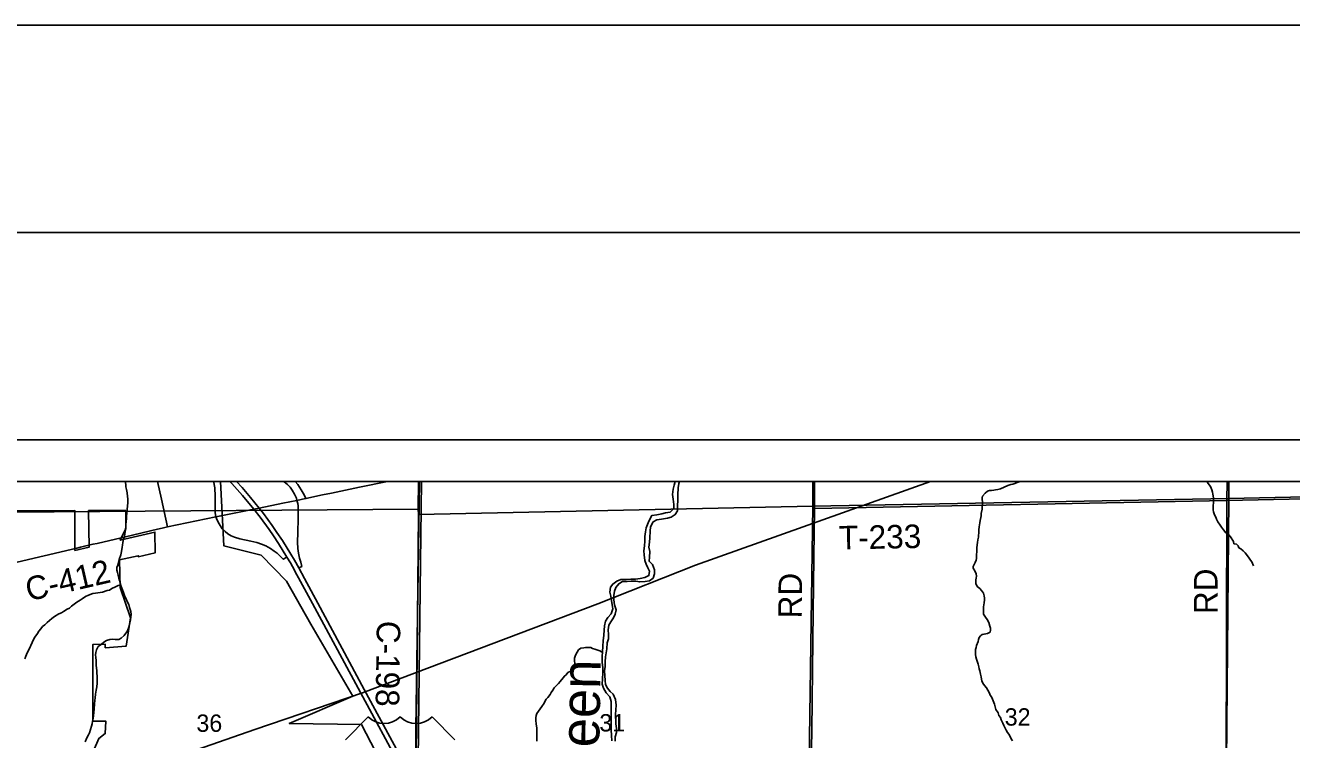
# Model space of a CAD drawing. Extents: x 36.7 to 70.7, y 0 to 22.
# Drawn here: x 40.424 to 43.478, y 20.274 to 21.997 of the extents above; entities that cross this region are included whole.
import ezdxf

# ---------------------------------------------------------------- set-up
doc = ezdxf.new("R2010")
doc.units = 0
for name, color, linetype in [('Default', 7, 'Continuous'), ('GM_X_City_Street', 7, 'Continuous'), ('GM_X_County_Road', 7, 'Continuous'), ('GM_X_County_Road_Text', 7, 'Continuous'), ('GM_X_Interchange_Ramps', 7, 'Continuous'), ('GM_X_Minor_River', 7, 'Continuous'), ('GM_X_Minor_River_Text', 7, 'Continuous'), ('GM_X_Rail_Line', 7, 'Continuous'), ('GM_X_Section', 7, 'Continuous'), ('GM_X_Section_Text', 7, 'Continuous'), ('GM_X_State_Route', 7, 'Continuous'), ('GM_X_Township_Road', 7, 'Continuous'), ('GM_X_Township_Road_Text', 7, 'Continuous'), ('GM_X_US_Route', 7, 'Continuous'), ('GM_X_US_Shield', 7, 'Continuous'), ('SH_Border', 7, 'Continuous'), ('SH_Cut_Line', 7, 'Continuous'), ('SH_Data', 7, 'Continuous')]:
    doc.layers.add(name, color=color, linetype=linetype)

msp = doc.modelspace()

# ---------------------------------------------------------------- linework, layer by layer
at = {"layer": 'Default'}
for points in [[(41.36, 20.0684), (41.2347, 20.3107), (41.0604, 20.3126), (41.214, 20.3785), (41.1126, 20.5525), (41.0537, 20.6559), (40.9928, 20.719), (40.9027, 20.7415), (40.895, 20.8969), (40.3795, 20.8969)], [(40.3778, 20.8261), (40.5438, 20.8262), (40.5437, 20.7305), (40.5783, 20.7382), (40.5767, 20.8262), (40.6662, 20.8262), (40.6662, 20.783), (40.6532, 20.755), (40.7365, 20.7744), (40.7376, 20.7245), (40.6963, 20.7149), (40.6963, 20.7176), (40.6514, 20.7072), (40.6526, 20.6409), (40.6779, 20.5674), (40.6671, 20.4991), (40.617, 20.4956), (40.617, 20.5041), (40.5872, 20.5036), (40.5873, 20.3184), (40.6185, 20.3181), (40.6169, 20.2884), (40.6016, 20.2769), (40.5883, 20.2469)]]:
    msp.add_lwpolyline(points, dxfattribs=at)
for points in [[(41.3719, 20.8969), (40.3859, 20.8969), (40.3846, 20.8226), (41.3712, 20.8297)], [(42.3233, 20.8969), (41.3719, 20.8969), (41.3712, 20.8297), (41.3719, 20.8169), (42.3229, 20.8368)], [(43.3265, 20.8969), (42.3233, 20.8969), (42.3229, 20.8368), (43.3259, 20.8559)], [(44.3297, 20.8969), (43.3265, 20.8969), (43.3259, 20.8559), (44.3293, 20.877)]]:
    msp.add_lwpolyline(points, close=True, dxfattribs=at)
at = {"layer": 'GM_X_City_Street'}
msp.add_lwpolyline([(40.7671, 20.787), (40.7529, 20.8536), (40.7428, 20.8969)], dxfattribs=at)
at = {"layer": 'GM_X_County_Road'}
for points in [[(41.3724, 20.2907), (41.3724, 20.2976), (41.3772, 20.7013), (41.3795, 20.8969)], [(40.7545, 20.7841), (40.7671, 20.787), (40.8833, 20.811)], [(40.6661, 20.7634), (40.7428, 20.7814), (40.7545, 20.7841)], [(40.2321, 20.662), (40.5482, 20.7359), (40.5572, 20.738)], [(40.5572, 20.738), (40.5872, 20.745), (40.597, 20.7473)], [(40.597, 20.7473), (40.6553, 20.7609), (40.6661, 20.7634)], [(41.5658, 19.8236), (41.565, 19.832), (41.5635, 19.8393), (41.5617, 19.8452), (41.5575, 19.8561), (41.5522, 19.8667), (41.5429, 19.8845), (41.5299, 19.909), (41.5148, 19.9368), (41.4954, 19.9722), (41.4697, 20.0201), (41.4396, 20.0758), (41.4107, 20.1293), (41.3858, 20.1754), (41.3766, 20.1942), (41.3724, 20.2103), (41.3715, 20.2274), (41.3724, 20.2907)]]:
    msp.add_lwpolyline(points, dxfattribs=at)
at = {"layer": 'GM_X_Interchange_Ramps'}
for points in [[(41.0791, 20.851), (41.078, 20.8566), (41.0735, 20.8663), (41.0677, 20.8757), (41.0626, 20.8829), (41.0566, 20.8894), (41.0483, 20.8961), (41.0469, 20.8969)], [(41.0838, 20.6879), (41.0912, 20.6918), (41.0883, 20.7017), (41.0855, 20.7119), (41.0829, 20.7236), (41.0816, 20.7346), (41.0808, 20.7502), (41.0813, 20.7738), (41.082, 20.8072), (41.0823, 20.8252), (41.0823, 20.8375), (41.0815, 20.8433), (41.0791, 20.851)], [(40.8833, 20.811), (40.8851, 20.8071), (40.889, 20.7988), (40.8936, 20.7904), (40.8992, 20.7826), (40.9007, 20.7812)], [(40.9007, 20.7812), (40.9057, 20.776), (40.9128, 20.7702), (40.9205, 20.7657), (40.9289, 20.7619), (40.9417, 20.7584), (40.968, 20.7526), (40.9826, 20.7492), (40.9937, 20.7455), (41.0039, 20.741), (41.0151, 20.735), (41.0242, 20.7289), (41.0315, 20.7234), (41.039, 20.7165), (41.0462, 20.7089), (41.0547, 20.7144)]]:
    msp.add_lwpolyline(points, dxfattribs=at)
at = {"layer": 'GM_X_Minor_River'}
for points in [[(40.6653, 20.8969), (40.6662, 20.8894), (40.6669, 20.8837), (40.6683, 20.8769), (40.6694, 20.8693), (40.6704, 20.8601), (40.6711, 20.8544), (40.671, 20.8465), (40.6705, 20.8366), (40.6701, 20.8309), (40.6688, 20.8207), (40.668, 20.8123), (40.6679, 20.807), (40.6671, 20.7991), (40.6666, 20.7937), (40.6662, 20.7877), (40.6657, 20.7805), (40.6641, 20.7702), (40.6629, 20.7642), (40.6605, 20.7581), (40.6593, 20.7498), (40.6585, 20.7433), (40.6577, 20.738)], [(41.8964, 20.6562), (41.9058, 20.6544), (41.9191, 20.6556), (41.9294, 20.6572), (41.9379, 20.6634), (41.9412, 20.674), (41.9415, 20.6834), (41.9365, 20.6965), (41.9284, 20.7043), (41.929, 20.7142), (41.9298, 20.7278), (41.9278, 20.7381), (41.9293, 20.7506), (41.9299, 20.7608), (41.9307, 20.7764), (41.9318, 20.7874), (41.9378, 20.799), (41.947, 20.8044), (41.958, 20.8053), (41.9725, 20.8079), (41.9817, 20.8107), (41.9914, 20.8169), (41.9969, 20.8254), (41.9968, 20.8368), (41.9976, 20.8524), (41.9976, 20.8642), (41.998, 20.8809), (42.0002, 20.8918), (42.0016, 20.8969)], [(41.9915, 20.8969), (41.9887, 20.8879), (41.9862, 20.8778), (41.9847, 20.8649), (41.9867, 20.8542), (41.9878, 20.8413), (41.988, 20.8314), (41.979, 20.8225), (41.968, 20.8213), (41.9588, 20.8185), (41.9473, 20.8162), (41.9352, 20.8146), (41.93, 20.806), (41.9263, 20.797), (41.9215, 20.785), (41.9193, 20.7748), (41.9179, 20.7642), (41.9183, 20.7528), (41.9169, 20.7411), (41.9158, 20.729), (41.9163, 20.7194), (41.9178, 20.7061), (41.9214, 20.6973)], [(42.8251, 20.8969), (42.8232, 20.8962), (42.8156, 20.894), (42.8103, 20.8918), (42.8057, 20.8903), (42.8008, 20.8893), (42.7932, 20.8867), (42.7848, 20.883), (42.7756, 20.8789), (42.7695, 20.8774), (42.7638, 20.8767), (42.7597, 20.8757), (42.754, 20.875), (42.749, 20.8746), (42.7441, 20.8732), (42.7383, 20.8683), (42.7326, 20.8615)], [(43.2724, 20.8969), (43.2746, 20.894), (43.2787, 20.8883), (43.2817, 20.8841), (43.2851, 20.8761), (43.2865, 20.8708), (43.2876, 20.8662), (43.2883, 20.862), (43.289, 20.8567), (43.2889, 20.8457), (43.2884, 20.8381), (43.2887, 20.8332), (43.2887, 20.8278), (43.289, 20.8233), (43.292, 20.8164), (43.2946, 20.8107), (43.2968, 20.8057), (43.2994, 20.7996), (43.3053, 20.7916), (43.3083, 20.7863), (43.3132, 20.7797), (43.3192, 20.7729), (43.3252, 20.769), (43.33, 20.7629), (43.3371, 20.7518), (43.3386, 20.7464), (43.3446, 20.7452), (43.3484, 20.741), (43.3506, 20.7368), (43.3551, 20.7345), (43.3608, 20.7291), (43.3653, 20.7241), (43.3712, 20.7169), (43.3754, 20.7115), (43.3787, 20.7069), (43.3817, 20.7027), (43.3861, 20.6928)], [(42.7326, 20.8615), (42.7314, 20.857), (42.7317, 20.8524), (42.7324, 20.8479), (42.7319, 20.8403), (42.7315, 20.8346), (42.7311, 20.83), (42.7294, 20.8194), (42.729, 20.8137), (42.7282, 20.8096), (42.7266, 20.8024), (42.7258, 20.7967), (42.7245, 20.7868), (42.7233, 20.78), (42.7236, 20.7716), (42.7228, 20.7667), (42.7223, 20.7625), (42.7211, 20.7557), (42.7199, 20.7497), (42.7191, 20.744), (42.7186, 20.7368), (42.7185, 20.7284), (42.718, 20.7189), (42.7176, 20.7106), (42.7168, 20.7064), (42.7148, 20.7011), (42.7125, 20.6962), (42.7098, 20.6913), (42.7097, 20.6871), (42.7134, 20.6807), (42.7168, 20.6742), (42.7178, 20.6685), (42.7167, 20.6635), (42.7162, 20.6594), (42.7158, 20.6544), (42.7165, 20.6502), (42.7195, 20.6434), (42.7255, 20.6384), (42.73, 20.6334), (42.7348, 20.6273), (42.7363, 20.6208), (42.737, 20.6151), (42.7373, 20.6109), (42.7365, 20.6037), (42.7356, 20.5992), (42.7348, 20.5939), (42.7344, 20.5874), (42.7347, 20.5813), (42.735, 20.5764), (42.7395, 20.5691), (42.7432, 20.5638), (42.7473, 20.5565), (42.7502, 20.5478), (42.7513, 20.5424), (42.7513, 20.5383), (42.7508, 20.5333), (42.7443, 20.5296), (42.7402, 20.5289), (42.736, 20.5286), (42.7314, 20.5275), (42.7272, 20.5241), (42.7245, 20.52), (42.7226, 20.5158), (42.7214, 20.5109), (42.7178, 20.501), (42.717, 20.4965), (42.7151, 20.4912), (42.7153, 20.4794), (42.7164, 20.4737), (42.7178, 20.4676), (42.72, 20.4608), (42.7215, 20.4558), (42.7233, 20.4494), (42.7244, 20.4448), (42.7259, 20.4398), (42.7273, 20.4322), (42.7287, 20.4254), (42.7298, 20.4201), (42.7309, 20.4155), (42.7331, 20.4098), (42.7372, 20.4044), (42.7417, 20.3991), (42.7451, 20.3933), (42.7488, 20.3857), (42.751, 20.3811), (42.7536, 20.3769), (42.7562, 20.3712), (42.7595, 20.3636), (42.761, 20.3594), (42.7628, 20.3533), (42.7646, 20.3468), (42.7702, 20.3388), (42.7713, 20.3323), (42.7758, 20.3269), (42.7776, 20.322), (42.7809, 20.3136), (42.7835, 20.3079), (42.7895, 20.2964), (42.7925, 20.2915), (42.7958, 20.2869), (42.7999, 20.28)], [(40.6577, 20.738), (40.6564, 20.7274), (40.6544, 20.7195), (40.6505, 20.7085), (40.6473, 20.6949), (40.645, 20.6888), (40.6449, 20.6824), (40.6463, 20.6767), (40.6478, 20.671), (40.6496, 20.6637), (40.6514, 20.6576), (40.6529, 20.6515), (40.6551, 20.6435), (40.6584, 20.6355), (40.6617, 20.6264), (40.6643, 20.6195), (40.6672, 20.6134), (40.6694, 20.6069), (40.6739, 20.5997), (40.6757, 20.5928), (40.6783, 20.5833), (40.679, 20.5761), (40.6781, 20.5632), (40.6765, 20.556), (40.6737, 20.5454), (40.6713, 20.539), (40.6686, 20.5337), (40.6621, 20.5254), (40.6556, 20.519), (40.6494, 20.5157), (40.6411, 20.5154), (40.6354, 20.5162), (40.6282, 20.5155), (40.6202, 20.5129), (40.6133, 20.5088), (40.6072, 20.5036), (40.5999, 20.4984), (40.5961, 20.4908), (40.5945, 20.4844), (40.5933, 20.4787), (40.5939, 20.4722), (40.595, 20.465), (40.5953, 20.4582), (40.5952, 20.4529), (40.5962, 20.4403), (40.5965, 20.4331), (40.5972, 20.4274), (40.5975, 20.4202), (40.5974, 20.4103), (40.5966, 20.4012), (40.5953, 20.3929), (40.5937, 20.3838), (40.5925, 20.3751), (40.5916, 20.3686), (40.5908, 20.3599), (40.5899, 20.347), (40.5882, 20.3318), (40.5877, 20.3246), (40.5865, 20.3182), (40.5853, 20.3121), (40.5837, 20.3061), (40.581, 20.2981), (40.5786, 20.2906), (40.5763, 20.2853), (40.5728, 20.2781), (40.5685, 20.2683)], [(41.9214, 20.6973), (41.9249, 20.6885), (41.9296, 20.68), (41.9278, 20.6698), (41.9182, 20.6647), (41.9064, 20.6624), (41.8954, 20.6612), (41.8844, 20.6611), (41.8726, 20.6603), (41.8604, 20.6598), (41.8501, 20.6563), (41.8408, 20.649), (41.8349, 20.6416), (41.8338, 20.6298), (41.8362, 20.6203), (41.8375, 20.6092), (41.8395, 20.5993), (41.8411, 20.5898), (41.8366, 20.5777), (41.8284, 20.5685), (41.8229, 20.5599), (41.8206, 20.5482), (41.8196, 20.5383), (41.8189, 20.5258), (41.8174, 20.5122), (41.8167, 20.4993), (41.8159, 20.486), (41.8152, 20.4743), (41.8152, 20.461), (41.8168, 20.4473), (41.8168, 20.4347), (41.8157, 20.4203), (41.8149, 20.4078), (41.8181, 20.3979), (41.8246, 20.3871), (41.8335, 20.3773), (41.8366, 20.3655), (41.8366, 20.3548), (41.8371, 20.3438), (41.8372, 20.3343), (41.837, 20.3241), (41.8366, 20.3108), (41.837, 20.2979), (41.8378, 20.2842), (41.8382, 20.2713)], [(40.6542, 20.6464), (40.6483, 20.6455), (40.6414, 20.6425), (40.6326, 20.6381), (40.6269, 20.6347), (40.6212, 20.6333), (40.6101, 20.6296), (40.6048, 20.6289), (40.5934, 20.6271), (40.587, 20.6264), (40.5767, 20.6227), (40.5694, 20.619), (40.5614, 20.6138), (40.5561, 20.6104), (40.548, 20.6052), (40.5358, 20.5962), (40.5304, 20.5913), (40.5247, 20.5884), (40.5163, 20.5831), (40.511, 20.5794), (40.5049, 20.5772), (40.4945, 20.5709), (40.4877, 20.566), (40.4769, 20.5562), (40.4712, 20.551), (40.4658, 20.5465), (40.4612, 20.5408), (40.4566, 20.5356), (40.4539, 20.5303), (40.4473, 20.5212), (40.4435, 20.5152), (40.4403, 20.508), (40.4333, 20.4922), (40.4287, 20.4831), (40.4252, 20.4755), (40.4228, 20.4691)], [(41.8465, 20.2703), (41.8468, 20.2809), (41.8497, 20.2907), (41.8496, 20.3009), (41.848, 20.312), (41.8483, 20.323), (41.8475, 20.3348), (41.8478, 20.3458), (41.8485, 20.3568), (41.8469, 20.3705), (41.842, 20.3839), (41.8346, 20.3898), (41.8283, 20.3983), (41.8229, 20.4069), (41.8224, 20.4167), (41.8212, 20.4285), (41.8211, 20.4399), (41.8222, 20.4505), (41.8221, 20.4619), (41.8228, 20.4733), (41.8246, 20.4831), (41.8264, 20.4933), (41.8271, 20.5074), (41.83, 20.5172), (41.8303, 20.5278), (41.8295, 20.5388), (41.8313, 20.5498), (41.8361, 20.5584), (41.8424, 20.5677), (41.8468, 20.5763), (41.849, 20.5873), (41.8451, 20.5991), (41.8436, 20.6113), (41.8435, 20.6212), (41.8445, 20.6322), (41.8482, 20.6412), (41.8553, 20.6501), (41.8645, 20.6552), (41.8751, 20.6556), (41.885, 20.6558), (41.8964, 20.6562)], [(41.8159, 20.4849), (41.8137, 20.4853), (41.8095, 20.4884), (41.8024, 20.4908), (41.7974, 20.492), (41.7922, 20.4935), (41.7876, 20.4959), (41.7804, 20.4963), (41.7751, 20.496), (41.7706, 20.4957), (41.7637, 20.4946), (41.7584, 20.4905), (41.7549, 20.4845), (41.7518, 20.4792), (41.7502, 20.475), (41.7486, 20.4701), (41.7486, 20.4644), (41.7489, 20.4568), (41.7473, 20.45), (41.743, 20.444), (41.7396, 20.4394), (41.7327, 20.4357), (41.7285, 20.4305), (41.7239, 20.4271), (41.7212, 20.4226), (41.7142, 20.4143), (41.71, 20.409), (41.6996, 20.3989), (41.6958, 20.3932), (41.6923, 20.3872), (41.6896, 20.3827), (41.6842, 20.3759), (41.68, 20.3714), (41.678, 20.3672), (41.6749, 20.3616), (41.6699, 20.3536), (41.6657, 20.348), (41.6615, 20.3427), (41.6576, 20.3371), (41.6556, 20.3322), (41.6552, 20.3261), (41.6555, 20.3208), (41.6562, 20.3113), (41.6565, 20.3071), (41.6572, 20.3014), (41.6579, 20.2953), (41.6577, 20.2756), (41.6572, 20.2699)], [(42.7999, 20.28), (42.8014, 20.2758), (42.8044, 20.2708)]]:
    msp.add_lwpolyline(points, dxfattribs=at)
at = {"layer": 'GM_X_Rail_Line'}
msp.add_lwpolyline([(39.9505, 19.9142), (40.5737, 20.1578), (40.9777, 20.2985), (41.2372, 20.3864), (41.8047, 20.6015), (42.0399, 20.6949), (42.6066, 20.8969)], dxfattribs=at)
at = {"layer": 'GM_X_Section'}
for points in [[(44.3293, 20.877), (44.3136, 19.8697), (44.2753, 19.8692), (43.3171, 19.855), (43.3259, 20.8559)], [(41.3712, 20.8297), (41.3719, 20.8169), (41.3623, 19.8182), (40.3573, 19.8404), (40.3846, 20.8226)], [(42.3229, 20.8368), (42.3088, 19.8313), (42.2743, 19.8312), (41.3623, 19.8182), (41.3719, 20.8169)], [(43.3259, 20.8559), (43.3171, 19.855), (43.2807, 19.8534), (42.3088, 19.8313), (42.3229, 20.8368)]]:
    msp.add_lwpolyline(points, close=True, dxfattribs=at)
at = {"layer": 'GM_X_State_Route'}
for p, q in [((41.0452, 20.8441), (41.0791, 20.851)), ((41.0791, 20.851), (41.0997, 20.8553)), ((40.8833, 20.811), (40.948, 20.8244))]:
    msp.add_line(p, q, dxfattribs=at)
for points in [[(40.8777, 20.8969), (40.8784, 20.8946), (40.8795, 20.8891)], [(40.8795, 20.8891), (40.8811, 20.881), (40.8821, 20.8615), (40.8819, 20.8385), (40.8819, 20.8215), (40.8833, 20.811)], [(41.0838, 20.6879), (41.0731, 20.7067), (41.0644, 20.7214), (41.0442, 20.7542), (41.031, 20.7739), (41.0195, 20.7904), (40.9981, 20.8196), (40.9882, 20.8326), (40.9672, 20.8582), (40.9469, 20.8819), (40.9335, 20.8969)], [(41.1409, 20.8641), (41.1626, 20.8687), (41.2303, 20.8829), (41.2977, 20.8969)], [(41.0997, 20.8553), (41.1008, 20.8555), (41.1409, 20.8641)], [(40.948, 20.8244), (40.9755, 20.8301), (40.9882, 20.8326), (41.0452, 20.8441)], [(41.5505, 19.8235), (41.5434, 19.8359), (41.5307, 19.8596), (41.3813, 20.1368), (41.3666, 20.1637), (41.3465, 20.201), (41.3138, 20.2614), (41.2416, 20.395), (41.1297, 20.6027), (41.0973, 20.6627), (41.0838, 20.6879)]]:
    msp.add_lwpolyline(points, dxfattribs=at)
at = {"layer": 'GM_X_Township_Road'}
for p, q in [((43.3216, 20.8505), (43.3224, 20.8969)), ((43.3216, 20.8505), (43.8254, 20.861)), ((42.3271, 20.8313), (43.3216, 20.8505)), ((43.3192, 19.8488), (43.3216, 20.8505))]:
    msp.add_line(p, q, dxfattribs=at)
for points in [[(40.1721, 19.8397), (40.7272, 19.8287), (40.7387, 19.8285), (40.7924, 19.8275), (40.7997, 19.8273), (40.8514, 19.8263), (40.8614, 19.8261), (41.3623, 19.8162), (41.3626, 19.8228), (41.3628, 19.8405), (41.3629, 19.8535), (41.3659, 20.06), (41.3665, 20.1284), (41.3664, 20.1389), (41.3664, 20.1643), (41.3664, 20.1648), (41.3661, 20.3009), (41.3748, 20.8969), (38.7934, 20.8969)], [(41.1008, 20.8555), (41.0965, 20.8647), (41.0896, 20.8762), (41.0811, 20.8896), (41.075, 20.8969)], [(45.5934, 20.8969), (41.3748, 20.8969), (41.3661, 20.3009), (41.3664, 20.1648), (41.3664, 20.1643), (41.3664, 20.1389), (41.3665, 20.1284), (41.3659, 20.06), (41.3629, 19.8535), (41.3628, 19.8405), (41.3626, 19.8228), (41.3623, 19.8162), (41.3671, 19.8162), (41.5405, 19.8156), (41.5474, 19.8155), (41.5546, 19.8154), (41.5623, 19.8154), (42.2762, 19.8294), (42.3137, 19.8294), (42.3685, 19.83), (42.7713, 19.8373), (43.2806, 19.8481), (43.3189, 19.8494), (44.0245, 19.8612)], [(42.3139, 19.8289), (42.3169, 20.0878), (42.3206, 20.2949), (42.3235, 20.5136), (42.3259, 20.7139), (42.3271, 20.8313), (42.3273, 20.8969)]]:
    msp.add_lwpolyline(points, dxfattribs=at)
at = {"layer": 'GM_X_US_Route'}
for points in [[(40.9173, 20.8969), (40.9223, 20.8918), (40.9477, 20.8627), (40.9755, 20.8301)], [(40.9335, 20.8969), (40.9469, 20.8819), (40.9672, 20.8582), (40.9882, 20.8326), (40.9981, 20.8196), (41.0195, 20.7904), (41.031, 20.7739), (41.0442, 20.7542), (41.0644, 20.7214), (41.0731, 20.7067), (41.0838, 20.6879)], [(40.9755, 20.8301), (40.9903, 20.8102), (41.0119, 20.7807), (41.0224, 20.7653), (41.0343, 20.7472), (41.0547, 20.7144), (41.0632, 20.7001), (41.073, 20.6827), (41.0744, 20.6801)], [(41.0744, 20.6801), (41.0878, 20.6556), (41.1166, 20.602), (41.3368, 20.194), (41.3667, 20.1383), (41.3705, 20.1311), (41.4092, 20.0595)], [(41.0838, 20.6879), (41.0973, 20.6627), (41.1297, 20.6027), (41.2416, 20.395), (41.3138, 20.2614), (41.3465, 20.201), (41.3666, 20.1637), (41.3813, 20.1368), (41.5307, 19.8596), (41.5434, 19.8359), (41.5505, 19.8235)]]:
    msp.add_lwpolyline(points, dxfattribs=at)
at = {"layer": 'GM_X_US_Shield'}
for p, q in [((41.2511, 20.3287), (41.1961, 20.2738)), ((41.4598, 20.2738), (41.4049, 20.3287))]:
    msp.add_line(p, q, dxfattribs=at)
for centre in [(41.2895, 20.3679), (41.3664, 20.3679)]:
    msp.add_arc(centre, 0.0549, 225.573, 314.427, dxfattribs=at)
at = {"layer": 'SH_Border'}
msp.add_lwpolyline([(38.1934, 21.4969), (70.1934, 21.4969), (70.1934, 0.4969), (38.1934, 0.4969)], close=True, dxfattribs=at)
at = {"layer": 'SH_Cut_Line'}
msp.add_lwpolyline([(36.6934, -0.0031), (70.6934, -0.0031), (70.6934, 21.9969), (36.6934, 21.9969)], close=True, dxfattribs=at)
at = {"layer": 'SH_Data'}
for p, q in [((38.6934, 20.9969), (45.6934, 20.9969)), ((38.7934, 20.8969), (45.5934, 20.8969))]:
    msp.add_line(p, q, dxfattribs=at)

# ---------------------------------------------------------------- texts
at = {"layer": 'GM_X_County_Road_Text'}
for s, rotation, p in [('C-412', 13.0365, (40.4319, 20.6073)), ('C-198', 269.1731, (41.2718, 20.5608))]:
    msp.add_text(s, height=0.05682, rotation=rotation, dxfattribs=at).set_placement(p)
at = {"layer": 'GM_X_Minor_River_Text'}
msp.add_text('Green', height=0.09475, rotation=88.8302, dxfattribs=at).set_placement((41.8048, 20.114))
at = {"layer": 'GM_X_Section_Text'}
for s, p in [('32', (42.7859, 20.3077)), ('36', (40.8367, 20.2927)), ('31', (41.8084, 20.2936))]:
    msp.add_text(s, height=0.04186, rotation=0, dxfattribs=at).set_placement(p)
at = {"layer": 'GM_X_Township_Road_Text'}
for s, rotation, p in [('T-233', 1.1237, (42.3866, 20.7324)), ('RD', 90, (43.299, 20.5768)), ('RD', 89.5063, (42.2965, 20.5662))]:
    msp.add_text(s, height=0.05682, rotation=rotation, dxfattribs=at).set_placement(p)

doc.saveas('drawing.dxf')
